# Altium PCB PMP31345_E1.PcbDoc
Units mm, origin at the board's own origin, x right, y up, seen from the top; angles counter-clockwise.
Board outline 47.37 x 92.08 mm, 2 copper layers (Top Layer, Bottom Layer); 57 components, 29 nets, 142 pads, 90 vias.
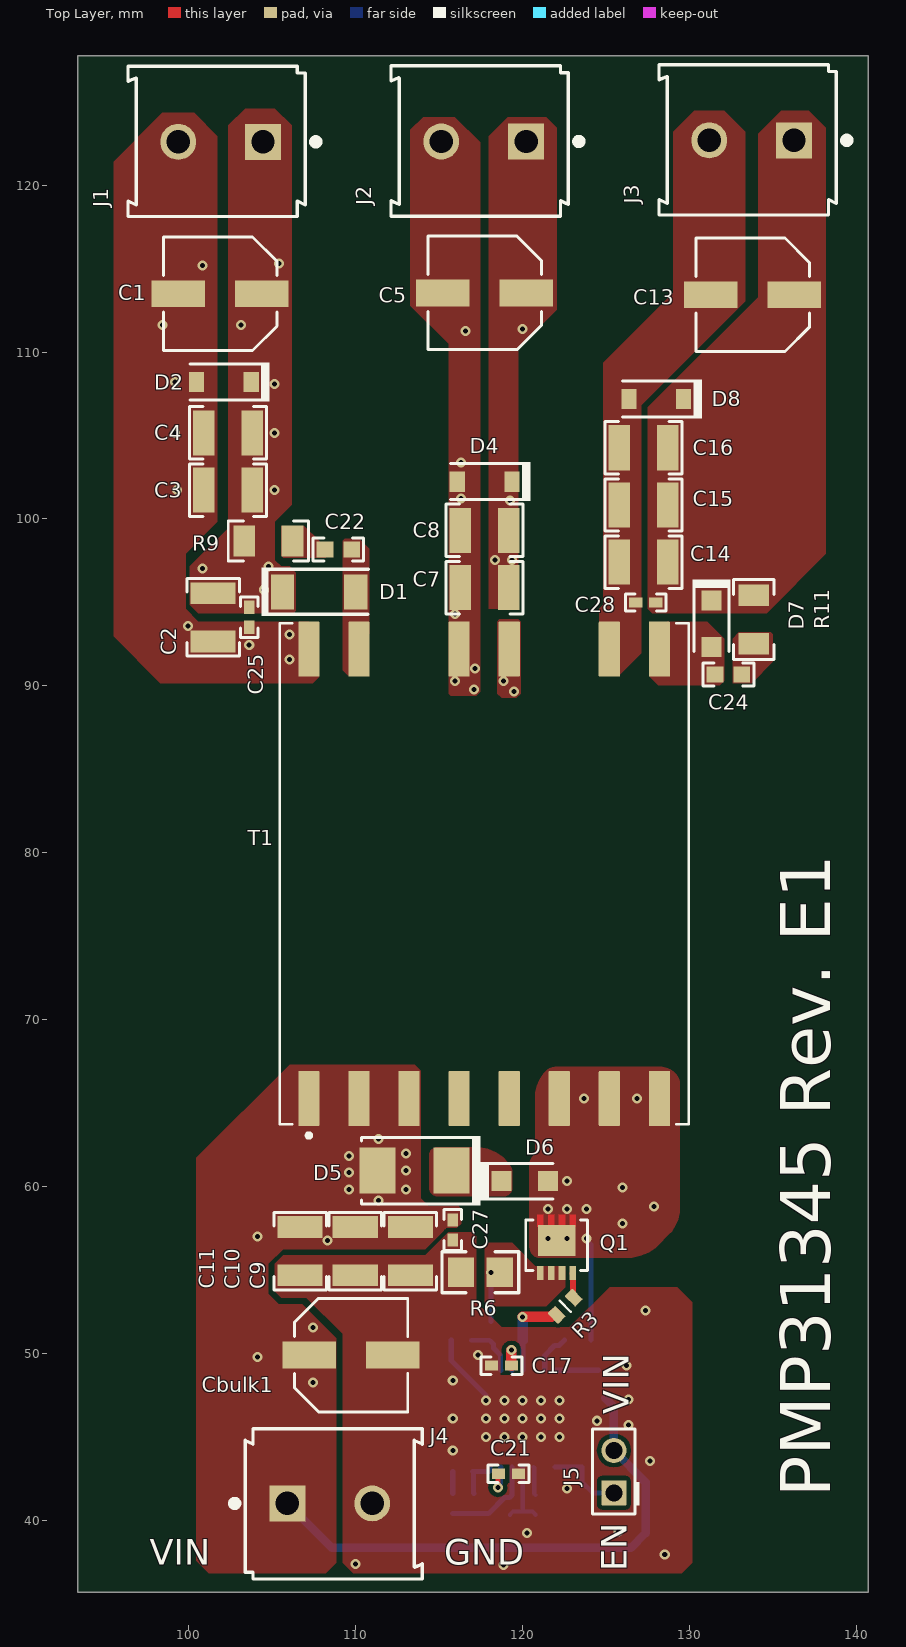
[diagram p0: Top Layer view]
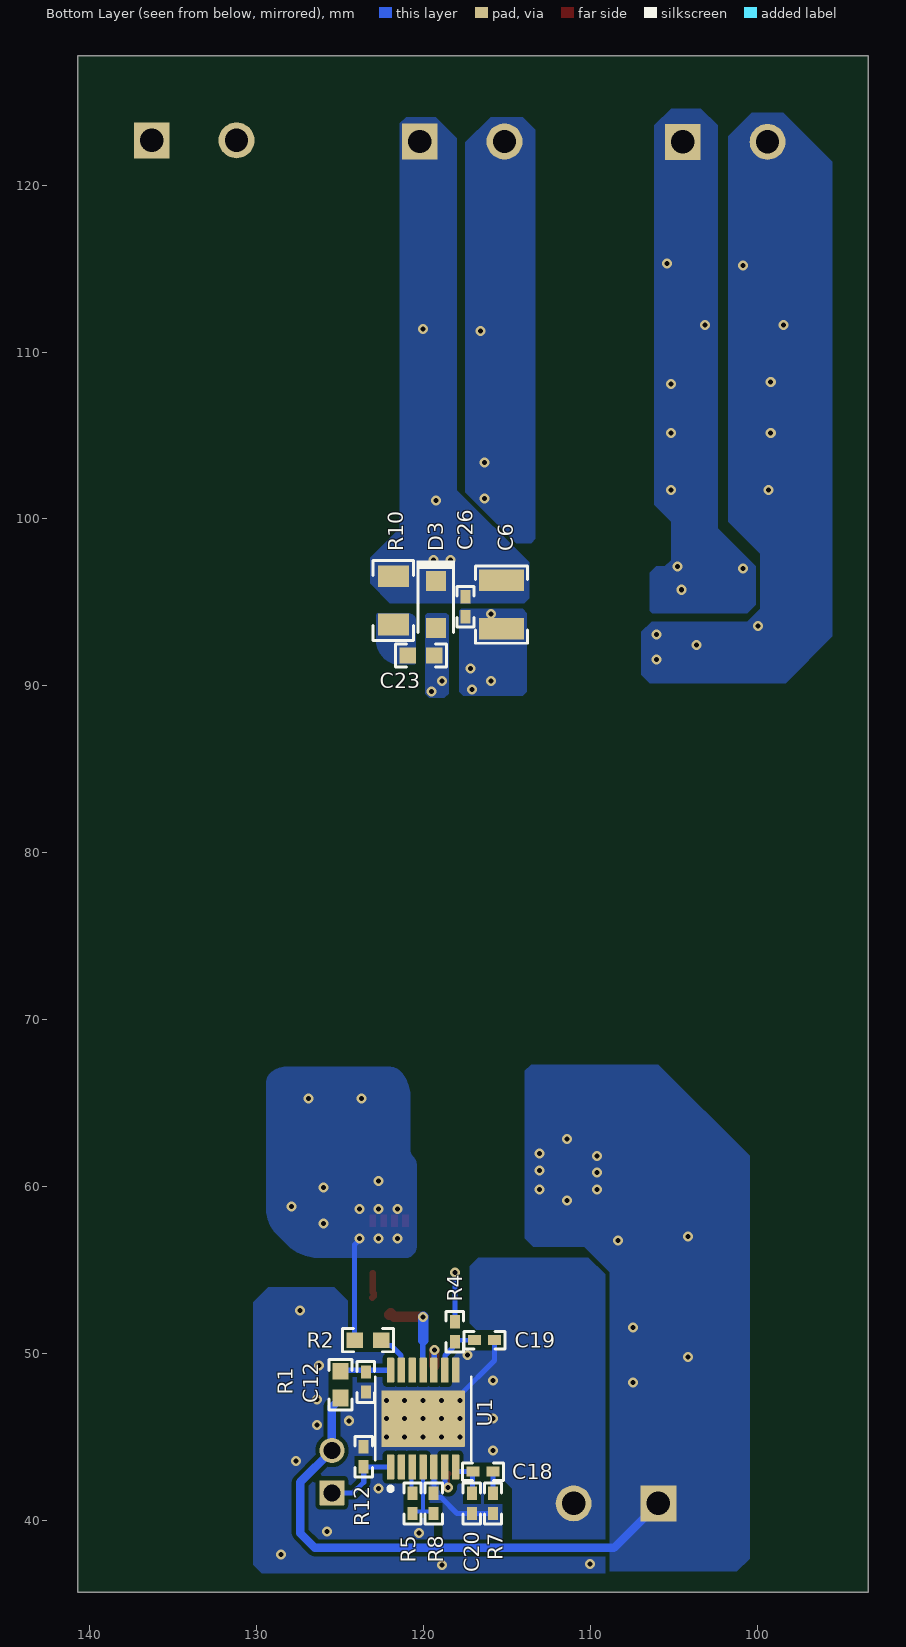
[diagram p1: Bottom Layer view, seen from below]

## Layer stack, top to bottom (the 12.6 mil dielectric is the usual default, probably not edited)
Top Solder: solder mask 0.0102, Solder Resist, Dk 3.5
Top Layer: signal copper 0.0356
Dielectric 1: dielectric 0.32, FR-4, Dk 4.8
Bottom Layer: signal copper 0.0356
Bottom Solder: solder mask 0.0102, Solder Resist, Dk 3.5

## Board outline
93.345,35.687 93.345,127.762 140.716,127.762 140.716,35.687

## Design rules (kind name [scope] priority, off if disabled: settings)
Clearance [All] p1: gap=0.254 ignorepadtopadclearanceinfootprint=FALSE
MinimumAnnularRing [All] p1: minimumring=0.15
PlaneConnect [All] p1: planeconnectstyle=Direct reliefexpansion=0.508 reliefentries=4 reliefconductorwidth=0.254 reliefairgap=0.254
PolygonConnect [All] p1: connectstyle=Direct reliefconductorwidth=0.254 reliefentries=4 polygonreliefangle="90 Angle" airgapwidth=0.254
RoutingVias [All] p1: holewidth=0.3 width=0.6 viastyle="Through Hole" minholewidth=0.3 minwidth=0.6 maxholewidth=0.711 maxwidth=1.27
SolderMaskExpansion [All] p1: expansion=0.102 istentingtop=FALSE
Width [All] p1: maxlimit=2.54 minlimit=0.254 preferedwidth=0.254 minimp=50.000000 maximp=50.000000 favimp=50.000000
29 further rules are at their usual default settings.

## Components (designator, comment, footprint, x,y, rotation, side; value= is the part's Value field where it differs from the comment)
C1 "EEE-FK1V470P" SM_RADIAL_D 101.891,113.493 r180 top value=47uF
C2 "UMJ325KB7106KMHT" 1210_270 101.473,94.107 r270 top value=10uF
C3 "UMJ325KB7106KMHT" 1210_270 102.362,101.727 r180 top value=10uF
C4 "UMJ325KB7106KMHT" 1210_270 102.362,105.156 r180 top value=10uF
C5 "EEE-FK1V470P" SM_RADIAL_D 117.729,113.538 r180 top value=47uF
C6 "UMJ325KB7106KMHT" 1210_270 115.316,94.869 r270 bottom value=10uF
C7 "UMJ325KB7106KMHT" 1210_270 117.729,95.885 r180 top value=10uF
C8 "UMJ325KB7106KMHT" 1210_270 117.729,99.314 r180 top value=10uF
C9 "GCM32ER71H475KA55L" 1210_270 113.284,56.134 r270 top value=4.7uF
C10 "GCM32ER71H475KA55L" 1210_270 109.982,56.134 r270 top value=4.7uF
C11 "GCM32ER71H475KA55L" 1210_270 106.68,56.134 r270 top value=4.7uF
C12 "CGA2B3X7R1H104K050BD" 0402 123.444,48.295 r270 bottom value=0.1uF
C13 "EEE-FK1V470P" SM_RADIAL_D 133.788,113.427 r180 top value=47uF
C14 "UMJ325KB7106KMHT" 1210_270 127.254,97.409 r180 top value=10uF
C15 "UMJ325KB7106KMHT" 1210_270 127.254,100.838 r180 top value=10uF
C16 "UMJ325KB7106KMHT" 1210_270 127.254,104.267 r180 top value=10uF
C17 "GRT155C81C225ME13D" 0402 118.745,49.276 r180 top value=2.2uF
C18 "GCM155R71E223KA55D" 0402 116.424,42.926 r180 bottom value=0.022uF
C19 "CGA2B2C0G1H101J050BA" 0402 116.332,50.8 r180 bottom value=100pF
C20 "CGA2B2C0G1H220J050BA" 0402 117.094,41.021 r270 bottom value=22pF
C21 "CGA2B2X8R1H102K050BA" 0402 119.161,42.799 r0 top value=1000pF
C22 "251R14S220JV4T" 0603 108.966,98.171 r0 top value=22pF
C23 "251R14S220JV4T" 0603 120.142,91.821 r180 bottom value=22pF
C24 "251R14S220JV4T" 0603 132.334,90.678 r180 top value=22pF
C25 "GCM155R71H104KE02D" 0402 103.632,94.107 r270 top value=0.1uF
C26 "GCM155R71H104KE02D" 0402 117.475,94.742 r270 bottom value=0.1uF
C27 "GCM155R71H104KE02D" 0402 115.824,57.404 r270 top value=0.1uF
C28 "GCM155R71H104KE02D" 0402 127.381,94.996 r180 top value=0.1uF
Cbulk1 "EEE-FK1V470P" SM_RADIAL_D 109.728,49.911 r0 top value=47uF
D1 "PMEG6030EVPX" SOD-128 107.823,95.631 r0 top value=60V
D2 "DDZ23Q-7" SOD-123 102.108,108.204 r180 top value=23V
D3 "PMEG6020ER,115" SOD-123W 119.253,94.869 r270 bottom value=60V
D4 "DDZ23Q-7" SOD-123 117.729,102.235 r180 top value=23V
D5 "VS-10BQ030HM3/5BT" SMB 113.538,60.96 r180 top value=30V
D6 "PMEG10020ELRX" SOD-123W 120.142,60.325 r0 top value=100V
D7 "PMEG6020ER,115" SOD-123W 131.318,93.726 r270 top value=60V
D8 "DDZ23Q-7" SOD-123 128.016,107.188 r180 top value=23V
J1 "282841-2" TEC_282841-2 101.919,122.592 r180 top
J2 "282841-2" TEC_282841-2 117.677,122.614 r180 top
J3 "282841-2" TEC_282841-2 133.731,122.682 r180 top
J4 "282841-2" TEC_282841-2 108.458,41.021 r0 top
J5 "PEC02SAAN" CONN_PEC02SAAN 125.476,42.926 r90 top
Q1 "BUK9M35-80E" LFPAK33 122.047,56.388 r90 top value=30V
R1 "CRCW060310R0FKEA" 0603 124.968,48.133 r270 bottom value=10.0
R2 "CRCW0603221KFKEA" 0603 123.317,50.8 r0 bottom value=221k
R3 "0" FP-ERJ-H3G0R00V_0603-MFG 122.555,52.832 r45 top
R4 "RMCF0402JT100R" 0402 118.11,51.308 r90 bottom value=100
R5 "CRCW0402249KFKED" 0402 120.65,41.021 r90 bottom value=249k
R6 "PE1206FRF470R007L" PE1206 117.475,54.864 r0 top value=0.007
R7 "ERJPA2F1002X" 0402 115.824,41.021 r90 bottom value=10.0k
R8 "ERJPA2F1002X" 0402 119.38,41.021 r270 bottom value=10.0k
R9 "RC1206FR-07100RL" 1206 104.775,98.679 r180 top value=100
R10 "RC1206FR-07100RL" 1206 121.793,95.123 r90 bottom value=100
R11 "RC1206FR-07100RL" 1206 133.858,93.98 r90 top value=100
R12 "RMCF0402FT100K" 0402 123.571,43.815 r270 bottom value=100k
T1 "ZF3077-AE" FP-ZF3077-AE_SMD16-MFG 117.705,78.738 r90 top
U1 "LM5185QPWPRQ1" PWP0014G-MFG 120.015,46.101 r90 bottom

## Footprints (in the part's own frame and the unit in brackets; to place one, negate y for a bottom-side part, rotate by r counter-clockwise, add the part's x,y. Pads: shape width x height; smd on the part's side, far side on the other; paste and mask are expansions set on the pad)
0402 [mm] "0402 from SM-752 data"
  rect 0.8x0.6 smd: 1(-0.6,0) 2(0.6,0)
  silkscreen extent -1.22,-0.52 1.22,0.52, body extent -0.55,-0.3 0.55,0.3, height 0.6
0603 [mm] "0603 from SM-752 data"
  rect 1x0.95 smd: 1(-0.8,0) 2(0.8,0)
  silkscreen extent -1.52,-0.69 1.52,0.69, body extent -0.87,-0.47 0.87,0.47, height 1
1206 [mm] "1206 from SM-752 data"
  rect 1.3x1.85 smd: 1(-1.45,0) 2(1.45,0)
  silkscreen extent -2.4,-1.21 2.4,1.21, body extent -1.7,-0.9 1.7,0.9, height 1.35
1210_270 [mm] "1210"
  rect 1.3x2.7 smd: 1(-1.45,0) 2(1.45,0)
  silkscreen extent -2.32,-1.57 2.32,1.57, body extent -1.7,-1.35 1.7,1.35, height 2.7
CONN_PEC02SAAN [mm] "SULLINS"
  rrect7% 1.5x1.5 hole 1.016: 1(-1.27,0)
  round 1.5 hole 1.016: 2(1.27,0)
  silkscreen extent -2.54,-1.52 2.54,1.27, body extent -2.54,-1.27 2.54,1.27, height 8.38
FP-ERJ-H3G0R00V_0603-MFG [mm]
  rrect15% 0.65x0.9 smd paste+0 mask+0: 1(-0.725,0) 2(0.725,0)
  silkscreen extent 0,-0.48 0,0.48, body extent -1.15,-0.58 1.15,0.58, height 0.25
FP-ZF3077-AE_SMD16-MFG [mm]
  rrect8% 3.3x1.27 smd paste+0 mask+0: 1(-13.46,10.5) 2(-13.46,7.5) 3(-13.46,4.5) 4(-13.46,1.5) 5(-13.46,-1.5) 6(-13.46,-4.5) 7(-13.46,-7.5) 8(-13.46,-10.5) 9(13.46,-10.5) 10(13.46,-7.5) 12(13.46,-1.5) 13(13.46,1.5) 15(13.46,7.5) 16(13.46,10.5)
  silkscreen extent -15.8,-12.25 15,12.25, body extent -15.21,-12.35 15.21,12.35, height 0.25
LFPAK33 [mm] "Nexperia"
  rect 0.83x0.4 smd paste-0.2 mask+0.05: 1(-1.555,0.975) 2(-1.555,0.325) 3(-1.555,-0.325) 4(-1.555,-0.975)
  rect 1.85x2.25 smd paste-1 mask+0.05: 5(0.385,0)
  Top Layer region: 1.18,-0.775 1.18,-1.175 1.93,-1.175 1.93,-0.775
  Top Layer region: 1.18,-0.125 1.18,-0.525 1.93,-0.525 1.93,-0.125
  Top Layer region: 1.18,0.525 1.18,0.125 1.93,0.125 1.93,0.525
  Top Layer region: 1.18,1.175 1.18,0.775 1.93,0.775 1.93,1.175
  silkscreen extent -1.4,-1.85 1.6,1.85, body extent -1.67,-1.66 1.63,1.64, height 0.87
PE1206 [mm] "YAGEO"
  rect 1.57x1.78 smd: 1(-1.165,0) 2(1.165,0)
  silkscreen extent -2.3,-1.22 2.3,1.22, body extent -1.72,-0.92 1.72,0.92, height 0.89
PWP0014G-MFG [mm]
  rrect22% 1.5x0.45 smd paste+0 mask+0: 1(-2.9,1.95) 2(-2.9,1.3) 3(-2.9,0.65) 4(-2.9,0) 5(-2.9,-0.65) 6(-2.9,-1.3) 7(-2.9,-1.95) 8(2.9,-1.95) 9(2.9,-1.3) 10(2.9,-0.65) 11(2.9,0) 12(2.9,0.65) 13(2.9,1.3) 14(2.9,1.95)
  rrect3% 3.4x5 smd paste-1000 mask-1000: 15(0,0)
  silkscreen extent -4.32,-2.88 2.5,2.88, body extent -3.2,-2.5 3.2,2.5, height 1.2
SM_RADIAL_D [mm] "6.3 x 5.8mm:  Panasonic D"
  rect 3.2x1.6 smd: 1(-2.5,0) 2(2.5,0)
  silkscreen extent -3.4,-3.4 3.4,3.4, body extent -3.4,-3.4 3.4,3.4, height 6.1
SMB [mm] "Molded Diode, 2-Leads, Body 5.4x3.6mm, IPC Medium Density, based on OnSemi component dimensions"
  rect 2.159x2.743 smd: 1(-2.21,0) 2(2.21,0)
  silkscreen extent -3.94,-2.08 3.18,2.08, body extent -2.7,-1.8 2.7,1.8, height 2.32
SOD-123 [mm] "On Semi recommended land pattern"
  rect 0.915x1.22 smd: 1(-1.637,0) 2(1.637,0)
  silkscreen extent -2.74,-1.17 2.03,1.17, body extent -1.93,-0.9 1.93,0.9, height 1.35
SOD-123W [mm] "NXP recommended land pattern"
  rect 1.2x1.2 smd paste-0.05: 1(-1.4,0) 2(1.4,0)
  silkscreen extent -2.64,-1.14 1.68,1.14, body extent -1.85,-0.95 1.85,0.95, height 1.1
SOD-128 [mm] "SMD, 2-Leads, Body 4x2.7mm, Height 1.1mm"
  rect 1.4x2.1 smd paste-0.1: 1(-2.2,0) 2(2.2,0)
  silkscreen extent -3.45,-1.45 2.95,1.45, body extent -2.5,-1.35 2.5,1.35, height 1.11
TEC_282841-2 [mm] "TE Connectivity"
  rect 2.15x2.15 hole 1.4: 1(-2.54,0)
  round 2.15 hole 1.4: 2(2.54,0)
  silkscreen extent -5.9,-4.52 5.55,4.47, body extent -5.08,-4.52 5.58,4.48, height 15.2

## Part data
C1 C5 C13 Cbulk1: library part CMP-0010730-1, "CAP, AL, 47 uF, 35 V, +/- 20%, 0.36 ohm, AEC-Q200 Grade 2, SMD", Cap_Case=D, Manufacturer=Panasonic, Supplier Part Number 1=PCE3842CT-ND, Tolerance_%=20%, Value1="0.36 ohm", Value2=35V, ValueDisplayed=47uF
C2 C3 C4 C6 C7 C8 C14 C15 C16: library part CMP-0009257-2, "CAP, CERM, 10 uF, 50 V, +/- 10%, X7R, AEC-Q200 Grade 1, 1210", Cap_Case=1210, Manufacturer="Taiyo Yuden", Supplier Part Number 1=587-4279-1-ND, TempCo=X7R, Tolerance_%=10%, Value1=Unknown, Value2=50V, ValueDisplayed=10uF
C9 C10 C11: library part CMP-0750153-1, "CAP, CERM, 4.7 µF, 50 V,+/- 10%, X7R, AEC-Q200 Grade 1, 1210", Cap_Case=1210, Manufacturer=MuRata, TempCo=X7R, Tolerance_%=10%, Value2=50V, ValueDisplayed=4.7µF
C12: library part CMP-0084548-1, "CAP, CERM, 0.1 µF, 50 V,+/- 10%, X7R, AEC-Q200 Grade 1, 0402", Cap_Case=0402, Manufacturer=TDK, TempCo=X7R, Tolerance_%=10%, Value2=50V, ValueDisplayed=0.1µF
C17: library part CMP-0860190-1, "CAP, CERM, 2.2 µF, 16 V,+/- 20%, X6S, AEC-Q200 Grade 2, 0402", Cap_Case=0402, Manufacturer=MuRata, TempCo=X6S, Tolerance_%=20%, Value2=16V, ValueDisplayed=2.2µF
C18: library part CMP-0006353-2, "CAP, CERM, 0.022 uF, 25 V, +/- 10%, X7R, AEC-Q200 Grade 1, 0402", Cap_Case=0402, Manufacturer=MuRata, Supplier Part Number 1=490-6044-1-ND, TempCo=X7R, Tolerance_%=10%, Value1=Unknown, Value2=25V, ValueDisplayed=0.022uF
C19: library part CMP-0006308-2, "CAP, CERM, 100 pF, 50 V, +/- 5%, C0G/NP0, AEC-Q200 Grade 1, 0402", Cap_Case=0402, Manufacturer=TDK, Supplier Part Number 1=445-5596-1-ND, TempCo=C0G/NP0, Tolerance_%=5%, Value1=Unknown, Value2=50V, ValueDisplayed=100pF
C20: library part CMP-0860831-1, "CAP, CERM, 22 pF, 50 V,+/- 5%, C0G/NP0, AEC-Q200 Grade 1, 0402", Cap_Case=0402, Manufacturer=TDK, TempCo=C0G/NP0, Tolerance_%=5%, Value2=50V, ValueDisplayed=22pF
C21: library part CMP-0860997-1, "CAP, CERM, 1000 pF, 50 V,+/- 10%, X8R, AEC-Q200 Grade 0, 0402", Cap_Case=0402, Manufacturer=TDK, TempCo=X8R, Tolerance_%=10%, Value2=50V, ValueDisplayed=1000pF
C22 C23 C24: library part CMP-0081187-1, "CAP, CERM, 22 pF, 250 V,+/- 5%, C0G/NP0, AEC-Q200 Grade 1, 0603", Cap_Case=0603, Manufacturer="Johanson Technology", Supplier Part Number 1=712-1332-1-ND, TempCo=C0G/NP0, Tolerance_%=5%, Value2=250V, ValueDisplayed=22pF
C25 C26 C27 C28: library part CMP-0006356-2, "CAP, CERM, 0.1 uF, 50 V, +/- 10%, X7R, AEC-Q200 Grade 1, 0402", Cap_Case=0402, Manufacturer=MuRata, Supplier Part Number 1=490-10672-1-ND, TempCo=X7R, Tolerance_%=10%, Value1=Unknown, Value2=50V, ValueDisplayed=0.1uF
D1: library part CMP-0077008-3, "Diode, Schottky, 60 V, 3 A, SOD-128", Manufacturer=Nexperia, Value1=3A, Value2=0.475V
D2 D4 D8: library part CMP-0085153-1, "Diode, Zener, 23 V, 500 mW, AEC-Q101, SOD-123", Manufacturer="Diodes Inc.", Power_W=500mW, Value1=0.5W
D3 D7: library part CMP-0076989-2, "Diode, Schottky, 60 V, 2 A, SOD-123W", Manufacturer=Nexperia, Value1=2A, Value2=0.53V
D5: library part CMP-0028904-2, "Diode, Schottky, 30 V, 1 A, AEC-Q101, SMB", Manufacturer=Vishay-Semiconductor, Value1=1A, Value2=0.42V
D6: library part CMP-0028977-2, "Diode, Schottky, 100 V, 2 A, AEC-Q101, SOD-123W", Manufacturer=Nexperia, Value1=2A, Value2=0.83V
J1 J2 J3 J4: library part CMP-0054973-1, "Terminal Block, 2x1, 5.08mm, TH", Manufacturer="TE Connectivity", Supplier Part Number 1=A98342-ND
J5: library part CMP-0002337-1, "Header, 100mil, 2x1, Tin, TH", Color=Black, Current_A=3A, Manufacturer="Sullins Connector Solutions", Supplier Part Number 1=S1012E-02-ND, Voltage_V=1.8kV
Q1: library part CMP-0078414-2, "MOSFET, N-CH, 30 V, 70 A, AEC-Q101, 3.4x0.9x2.7mm", Alternate Manufacturer=None, Manufacturer=Nexperia, PartNumber=BUK9M6R6-30EX, Supplier Part Number 1=1727-2584-1-ND, Value1="? ohm", Value2="18 nC"
R1: library part CMP-0022003-4, "RES, 10.0, 1%, 0.1 W, AEC-Q200 Grade 0, 0603", Manufacturer=Vishay-Dale, Power_W=100mW, Supplier Part Number 1=541-10.0HCT-ND, TempCo="100 ppm/C", Tolerance_%=1%, Value2=0.1W, Value_Code=10R0, ValueDisplayed=10.0
R2: library part CMP-0022216-4, "RES, 221 k, 1%, 0.1 W, AEC-Q200 Grade 0, 0603", Manufacturer=Vishay-Dale, Power_W=100mW, Supplier Part Number 1=541-221KHCT-ND, TempCo="100 ppm/C", Tolerance_%=1%, Value2=0.1W, Value_Code=221k
R3: library part CMP-0097467-1, "0 Ohms Jumper 0.125W, 1/8W Chip Resistor 0603 (1608 Metric) Automotive AEC-Q200 Thick Film", Digikey Part Number=10-ERJ-H3G0R00VCT-ND, Manufacturer=Panasonic, Mouser Part Number=667-ERJ-H3G0R00V, Operating Temperature Range="-55°C to +175°C", Part Number=ERJ-H3G0R00V, Power_W=125mW
R4: library part CMP-0026763-1, "RES, 100, 1%, 0.063 W, AEC-Q200 Grade 0, 0402", Manufacturer="Stackpole Electronics Inc", Power_W=63mW, Supplier Part Number 1=RMCF0402JT100RCT-ND, TempCo="100 ppm/C", Tolerance_%=1%, Value2=0.063W, Value_Code=100R, ValueDisplayed=100
R5: library part CMP-0026193-2, "RES, 249 k, 1%, 0.063 W, AEC-Q200 Grade 0, 0402", Manufacturer=Vishay-Dale, Power_W=63mW, Supplier Part Number 1=541-249KLCT-ND, TempCo="100 ppm/C", Tolerance_%=1%, Value2=0.063W, Value_Code=249k
R6: library part CMP-0017834-2, "RES, 0.007, 1%, 1 W, AEC-Q200 Grade 0, 1206", Manufacturer="Yageo America", Power_W=1W, Supplier Part Number 1=PE1206FRF470R007L-ND, TempCo="100 ppm/C", Tolerance_%=1%, Value_Code=7L000, ValueDisplayed=0.007
R7 R8: library part CMP-0078779-1, "RES, 10.0 k, 1%, 0.2 W, AEC-Q200 Grade 0, 0402", Manufacturer=Panasonic, Power_W=200mW, Supplier Part Number 1=P17230CT-ND, TempCo="100 ppm/C", Tolerance_%=1%, Value2=0.2W, Value_Code=10k0, ValueDisplayed=10.0k
R9 R10 R11: library part CMP-0017837-2, "RES, 100, 1%, 0.25 W, 1206", Manufacturer="Yageo America", Power_W=250mW, Supplier Part Number 1=311-100FRCT-ND, TempCo="100 ppm/C", Tolerance_%=1%, Value2=0.25W, Value_Code=100R, ValueDisplayed=100
R12: library part CMP-0026753-1, "RES, 100 k, 1%, 0.063 W, AEC-Q200 Grade 0, 0402", Manufacturer="Stackpole Electronics Inc", Power_W=63mW, Supplier Part Number 1=RMCF0402FT100KCT-ND, TempCo="100 ppm/C", Tolerance_%=1%, Value2=0.063W, Value_Code=100k
T1: library part CMP-0122818-1, "Transformer", Frequency_Fixed=300kHz, Manufacturer=Coilcraft, Operating Temperature Range=to
U1: library part CMP-0120083-1, "100-VIN, PSR, Flyback, Automotive, DC/DC Controller With Low IQ and Low EMI", Manufacturer="Texas Instruments", Max Supply Voltage=100V, Min Supply Voltage=4.5V, Nominal Supply Current=25-425uA, Operating Temperature Range="-40°C to +125°C", Switching Frequency=10-350kHz

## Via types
v1: diameter 0.6, hole 0.3, Top Layer to Bottom Layer, 75 vias
v2: diameter 0.6, hole 0.3, Top Layer to Bottom Layer, tented both sides, 15 vias

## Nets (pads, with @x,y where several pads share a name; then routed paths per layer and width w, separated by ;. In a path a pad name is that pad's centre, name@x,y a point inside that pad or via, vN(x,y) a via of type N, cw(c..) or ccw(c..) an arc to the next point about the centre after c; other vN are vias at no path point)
GND: C9.2 C10.2 C11.2 C12.2 C17.2 C19.2 C20.2 C21.2 C27.2 Cbulk1.2 J4.2 R6.1 R7.1 R8.1 R12.1 U1.5 U1.8 U1.15 | length 10.2
  Bottom Layer w0.305: C19.2 115.732,49.584 117.815,47.501 v2(117.815,47.201) ; R7.1 117.977,40.421 118.93,41.373 119.232,41.373 119.38,41.521 R8.1 119.372,41.628 119.372,43.194 U1.5
  other v1: 118.872,37.338 110.008,37.384 128.524,37.973 120.269,39.243 125.759,39.335 122.682,41.91 127.635,43.561 115.824,44.196 126.365,45.72 124.46,45.974 115.824,46.101 126.365,47.244 115.824,48.387 126.238,49.276 117.348,49.911 127.381,52.578
  other v2: 117.815,45.001 118.915,45.001 120.015,45.001 121.115,45.001 122.215,45.001 117.815,46.101 118.915,46.101 120.015,46.101 121.115,46.101 122.215,46.101 118.915,47.201 120.015,47.201 121.115,47.201 122.215,47.201
GND22_1: C1.2 C2.2 C3.2 C4.2 C25.2 D2.2 J1.2 T1.16
  other v1: 106.045,91.567 103.632,92.456 106.045,93.091 99.949,93.599 99.314,101.727 99.187,105.156 99.187,108.204 98.425,111.633 100.838,115.189
GND22_2: C5.2 C6.2 C7.2 C8.2 C26.2 D4.2 J2.2 T1.13
  other v1: 117.094,89.789 115.951,90.297 117.165,91.028 115.956,94.313 116.332,101.219 116.332,103.378 116.586,111.252
GND22_3: C13.2 C14.2 C15.2 C16.2 C28.2 D8.2 J3.2 T1.10
NetC1_1: C1.1 C2.1 C3.1 C4.1 C25.1 D1.1 D2.1 J1.1 R9.2
  other v1: 104.521,95.758 100.838,97.028 104.775,97.155 105.156,101.727 105.156,105.156 105.156,108.077 103.124,111.633 105.41,115.316
NetC5_1: C5.1 C6.1 C7.1 C8.1 C26.1 D3.1 D4.1 J2.1 R10.2
  other v1: 118.364,97.536 119.38,97.536 119.253,101.092 120.015,111.379
NetC12_1: C12.1 R1.1 U1.14 | length 2.6
  Bottom Layer w0.305: U1.14 R1.1@124.566,49.001 ; R1.1 R1.1@124.968,48.958
NetC13_1: C13.1 C14.1 C15.1 C16.1 C28.1 D7.1 D8.1 J3.1 R11.2
NetC17_1: C17.1 U1.10 | length 2.1
  Top Layer w0.305: v1(119.33,50.202) v1@119.338,50.195 ; C17.1@119.338,49.283 C17.1
  Top Layer w0.635: C17.1@119.338,49.283 v1@119.338,50.195
  Bottom Layer w0.305: v1(119.33,50.202) 119.348,50.185 119.348,49.018 U1.10
NetC18_1: C18.1 C20.1 U1.7 | length 2.6
  Bottom Layer w0.305: C20.1 117.059,41.656 117.059,42.891 C18.1 117.992,42.926 118.065,42.999 U1.7
NetC18_2: C18.2 R7.2 | length 1.3
  Bottom Layer w0.305: R7.2 C18.2
NetC19_1: C19.1 R4.1 U1.9 | length 3.2
  Bottom Layer w0.254: C19.1 118.018,50.8 R4.1
  Bottom Layer w0.305: R4.1 118.258,50.56 118.258,50.329 118.696,49.89 118.696,49.02 U1.9
NetC21_1: C21.1 U1.6 | length 2.3
  Top Layer w0.305: C21.1@118.461,42.799 C21.1 118.543,42.781 118.543,41.986 v1(118.526,41.969)
  Bottom Layer w0.305: v1(118.526,41.969) 118.526,42.049 118.618,42.141 118.618,42.164 118.696,42.242 118.696,43.182 U1.6
NetC22_1: C22.1 R9.1
NetC22_2: C22.2 D1.2 T1.15
NetC23_1: C23.1 R10.1
NetC23_2: C23.2 D3.2 T1.12
  other v1: 119.507,89.662 118.872,90.297
NetC24_1: C24.1 R11.1
NetC24_2: C24.2 D7.2 T1.9
NetD5_1: D5.1 D6.1
NetJ5_1: J5.1 R12.2 U1.1 | length 4.7
  Bottom Layer w0.305: U1.1 121.979,43.215 R12.2 123.571,42.291 124.206,41.656 J5.1
NetQ1_1: Q1.1 Q1.2 Q1.3 R4.2 R6.2 | length 3
  Bottom Layer w0.305: R4.2 v1(118.11,54.864)
NetQ1_4: Q1.4 R3.2 | length 1.6
  Top Layer w0.305: Q1.4@122.979,54.79 Q1.4
  Top Layer w0.381: Q1.4@123.026,54.829 123.026,53.67 122.979,53.623 122.979,53.433 R3.2
NetR2_1: R2.1 U1.13 | length 2.5
  Bottom Layer w0.305: U1.13 121.334,49.02 121.334,49.89 121.921,50.477 122.194,50.477 R2.1
NetR3_1: R3.1 U1.11 | length 5.4
  Top Layer w0.635: v1(120.015,52.197) 121.733,52.197 121.943,52.408 121.954,52.408 R3.1
  Bottom Layer w0.305: U1.11 120.034,49.02 120.034,49.907 120.037,49.91 120.037,50.495 120.015,50.517 120.015,50.8
  Bottom Layer w0.635: 120.015,50.8 v1(120.015,52.197)
NetR5_1: R5.1 R8.2 U1.4 | length 4.4
  Bottom Layer w0.254: R8.2@119.253,40.329 119.253,40.362 119.426,40.535 120.015,40.535 ; U1.4 120.015,40.535 ; R5.1@120.777,40.329 120.777,40.362 120.604,40.535 120.015,40.535
NetR5_2: R5.2 U1.3 | length 1.7
  Bottom Layer w0.254: U1.3 120.709,43.157 120.709,41.597 R5.2@120.777,41.529
SW: D6.2 Q1.5 R2.2 T1.6 T1.7 T1.8 | length 6.2
  Bottom Layer w0.305: v1(123.825,56.896) 123.825,56.816 124.117,56.524 R2.2
  other v1: 121.539,56.896 122.682,56.896 125.984,57.785 121.539,58.674 122.682,58.674 123.825,58.674 127.889,58.801 125.984,59.944 122.682,60.325 123.698,65.278 126.873,65.278
Vin: C9.1 C10.1 C11.1 C27.1 Cbulk1.1 D5.2 J4.1 J5.2 R1.2 T1.1 T1.2 T1.3 | length 32
  Bottom Layer w0.508: J4.1 108.585,38.354 126.492,38.354 127.381,39.243 127.381,42.291 J5.2 125.476,46.8 124.968,47.308 R1.2
  other v1: 107.442,48.26 104.14,49.784 107.442,51.562 108.331,56.769 104.14,57.023 111.379,59.182 109.601,59.817 113.03,59.817 109.601,60.833 113.03,60.96 109.601,61.849 113.03,61.976 111.379,62.865
pads on no net: T1.4 T1.5 U1.2 U1.12

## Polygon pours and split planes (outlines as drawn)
GND on Top Layer "Top Layer-GND" (solid, pour order 39): 129.54,36.83 130.175,37.465 130.175,53.086 129.286,53.975 125.222,53.975 122.809,51.562 118.745,51.562 117.221,53.086 117.221,57.023 116.967,57.277 115.57,57.277 114.173,55.88 105.664,55.88 105.156,55.372 105.156,53.721 105.537,53.34 107.061,53.34 109.22,51.181 109.22,37.465 109.855,36.83 116.332,36.83
SW on Top Layer "NONET_L01_P-001" (solid, pour order 38): 126.329,55.753 ccw(c126.329,58.293) 128.125,56.497 128.778,57.15 ccw(c127.245,58.683) 129.413,58.683 129.413,66.189 ccw(c128.546,66.189) 129.159,66.802 ccw(c128.239,65.882) 128.239,67.183 122.025,67.183 ccw(c122.025,66.316) 121.412,66.929 ccw(c122.945,65.396) 120.777,65.396 120.777,62.156 cw(c120.343,62.156) 120.65,61.849 ccw(c121.263,61.236) 120.396,61.236 120.396,56.493 ccw(c121.263,56.493) 120.65,55.88 ccw(c120.957,56.187) 120.957,55.753
NetC1_1 on Top Layer "NONET_L01_P-001" (solid, pour order 36): 102.362,99.441 100.076,97.155 100.076,94.869 100.584,94.361 106.299,94.361 106.426,94.488 106.426,96.774 106.045,97.155 105.537,97.155 105.156,97.536 105.156,99.822 106.172,100.838 106.172,123.571 105.156,124.587 103.378,124.587 102.362,123.571
GND22_1 on Top Layer "NONET_L01_P-001" (solid, pour order 35): 107.188,93.853 100.584,93.853 99.822,94.615 99.822,97.917 101.727,99.822 101.727,122.936 100.33,124.333 98.425,124.333 95.504,121.412 95.504,92.964 98.298,90.17 107.442,90.17 107.823,90.551
GND22_2 on Top Layer "Top Layer-GND22_2" (solid, pour order 33): 113.284,112.776 115.57,110.49 115.57,89.535 115.697,89.408 117.221,89.408 117.475,89.662 117.475,122.555 115.951,124.079 114.046,124.079 113.284,123.317
Vin on Top Layer "Top Layer-Vin" (solid, pour order 28): 115.443,57.531 116.078,57.531 116.332,57.785 116.332,58.674 116.141,58.864 114.364,58.864 113.919,59.309 113.919,66.929 113.538,67.31 106.045,67.31 100.457,61.722 100.457,37.592 101.219,36.83 108.204,36.83 108.839,37.465 108.839,50.927 106.807,52.959 105.41,52.959 104.775,53.594 104.775,55.372 105.664,56.261 114.173,56.261
NetC23_2 on Top Layer "NONET_L01_P-001" (solid, pour order 23): 118.491,93.853 118.491,89.535 118.745,89.281 119.634,89.281 119.888,89.535 119.888,93.853 119.761,93.98 118.618,93.98
NetC24_1 on Top Layer "NONET_L01_P-001" (solid, pour order 18): 132.588,92.837 132.969,93.218 134.874,93.218 135.001,93.091 135.001,91.44 133.731,90.17 132.588,90.17
NetD5_1 on Top Layer "NONET_L01_P-001" (solid, pour order 17): 119.38,60.855 ccw(c118.513,60.855) 119.126,61.468 118.981,61.613 ccw(c117.185,59.817) 117.185,62.357 114.861,62.357 ccw(c114.861,61.923) 114.554,62.23 114.517,62.193 ccw(c114.734,61.976) 114.427,61.976 114.427,59.87 ccw(c114.861,59.87) 114.554,59.563 ccw(c114.861,59.87) 114.861,59.436 118.946,59.436 ccw(c118.946,59.87) 119.253,59.563 ccw(c118.946,59.87) 119.38,59.87 119.38,59.944
NetQ1_1 on Top Layer "NONET_L01_P-001" (solid, pour order 15): 122.555,55.245 120.777,55.245 119.38,56.642 117.983,56.642 117.729,56.388 117.729,53.086 117.983,52.832 121.412,52.832 122.555,53.975
NetC24_2 on Top Layer "NONET_L01_P-001" (solid, pour order 9): 128.651,93.853 131.064,93.853 132.08,92.837 132.08,90.297 131.826,90.043 128.143,90.043 127.635,90.551
NetC22_1 on Top Layer "NONET_L01_P-001" (solid, pour order 8): 108.331,97.663 105.664,97.663 105.537,97.79 105.537,99.568 106.934,99.568 107.823,98.679
NetC22_2 on Top Layer "NONET_L01_P-001" (solid, pour order 7): 110.827,93.14 110.827,98.215 110.236,98.806 109.347,98.806 109.22,98.679 109.22,90.932 109.601,90.551
NetC13_1 on Top Layer "NONET_L01_P-001" (solid, pour order 4): 127.508,106.68 134.112,113.284 134.112,123.063 135.509,124.46 137.16,124.46 138.176,123.444 138.176,97.917 134.62,94.361 127.762,94.361 127.508,94.615
GND22_3 on Top Layer "NONET_L01_P-001" (solid, pour order 3): 124.587,92.583 124.587,94.615 124.841,94.869 124.841,109.347 129.032,113.538 129.032,123.19 130.302,124.46 132.08,124.46 133.35,123.19 133.35,113.03 127.127,106.807 127.127,91.948 125.73,90.551
NetC5_1 on Top Layer "NONET_L01_P-001" (solid, pour order 1): 117.983,94.615 117.983,122.936 119.126,124.079 121.412,124.079 122.047,123.444 122.047,112.522 119.761,110.236 119.761,94.615
SW on Bottom Layer "NONET_L01_P-001" (solid, pour order 37): 126.329,55.753 ccw(c126.329,58.293) 128.125,56.497 128.778,57.15 ccw(c127.245,58.683) 129.413,58.683 129.413,66.189 ccw(c128.546,66.189) 129.159,66.802 ccw(c128.239,65.882) 128.239,67.183 122.025,67.183 ccw(c122.025,66.316) 121.412,66.929 ccw(c122.945,65.396) 120.777,65.396 120.777,62.156 cw(c120.343,62.156) 120.65,61.849 ccw(c121.263,61.236) 120.396,61.236 120.396,56.493 ccw(c121.263,56.493) 120.65,55.88 ccw(c120.957,56.187) 120.957,55.753
NetC1_1 on Bottom Layer "NONET_L01_P-001" (solid, pour order 6): 102.362,99.441 100.076,97.155 100.076,94.869 100.584,94.361 106.299,94.361 106.426,94.488 106.426,96.774 106.045,97.155 105.537,97.155 105.156,97.536 105.156,99.822 106.172,100.838 106.172,123.571 105.156,124.587 103.378,124.587 102.362,123.571
GND22_1 on Bottom Layer "NONET_L01_P-001" (solid, pour order 5): 106.936,93.23 106.313,93.853 100.584,93.853 99.822,94.615 99.822,97.917 101.727,99.822 101.727,122.936 100.33,124.333 98.425,124.333 95.504,121.412 95.504,92.964 98.298,90.17 106.426,90.17 106.936,90.68
GND22_2 on Bottom Layer "NONET_L01_P-001" (solid, pour order 34): 113.284,98.806 113.538,98.552 114.427,98.552 117.475,101.6 117.475,122.555 115.951,124.079 114.046,124.079 113.284,123.317
GND22_2 on Bottom Layer "NONET_L01_P-001" (solid, pour order 31): 117.729,94.615 117.856,94.488 117.856,89.662 117.602,89.408 114.046,89.408 113.792,89.662 113.792,94.361 114.046,94.615
NetC5_1 on Bottom Layer "NONET_L01_P-001" (solid, pour order 30): 113.968,94.947 121.998,94.947 123.19,96.139 123.19,97.663 121.412,99.441 121.412,123.698 121.031,124.079 119.253,124.079 117.983,122.809 117.983,101.727 113.665,97.409 113.665,95.25
NetC23_1 on Bottom Layer "NONET_L01_P-001" (solid, pour order 29): 120.457,91.434 120.457,93.914 cw(c120.904,93.914) 120.904,94.361 122.682,94.361 cw(c122.682,94.234) 122.809,94.234 122.809,92.676 cw(c121.419,92.676) 121.419,91.286 120.557,91.286 cw(c120.557,91.381) 120.462,91.381
Vin on Bottom Layer "NONET_L01_P-001" (solid, pour order 26): 110.363,56.388 108.839,54.864 108.839,36.957 101.219,36.957 100.457,37.719 100.457,61.849 105.918,67.31 113.538,67.31 113.919,66.929 113.919,56.896 113.411,56.388
GND on Bottom Layer "NONET_L01_P-001" (solid, pour order 25): 125.349,53.975 129.286,53.975 130.175,53.086 130.175,37.338 129.667,36.83 109.093,36.83 109.093,54.737 110.109,55.753 116.713,55.753 117.221,55.245 117.221,51.816 116.84,51.435 115.189,51.435 115.062,51.308 115.062,50.292 115.179,50.175 121.549,50.175
NetC23_2 on Bottom Layer "NONET_L01_P-001" (solid, pour order 24): 118.491,94.234 118.491,89.535 118.745,89.281 119.634,89.281 119.888,89.535 119.888,94.234 119.761,94.361 118.618,94.361

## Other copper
Bottom Layer:
  pour cut-out: 115.27,42.499 115.27,38.816 115.189,38.735 114.681,38.735 114.681,41.91
  pour cut-out: 118.826,39.767 118.827,39.766 118.827,38.868 119.374,38.868 119.38,38.862 119.38,39.751

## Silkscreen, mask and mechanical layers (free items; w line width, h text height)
Top Overlay:
  text "VIN" at 126.365,46.355 h1.52 r90
  text "PMP31345 Rev. E1" at 138.43,41.402 h3 r90
  text "VIN" at 97.663,37.338 h1.52
  text "GND" at 115.316,37.338 h1.52
  text "EN" at 126.238,36.957 h1.52 r90
Mechanical 1:
  lines w0.254: 93.345,35.687 93.345,127.762 130.429,127.762 140.716,127.762 140.716,35.687 93.345,35.687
